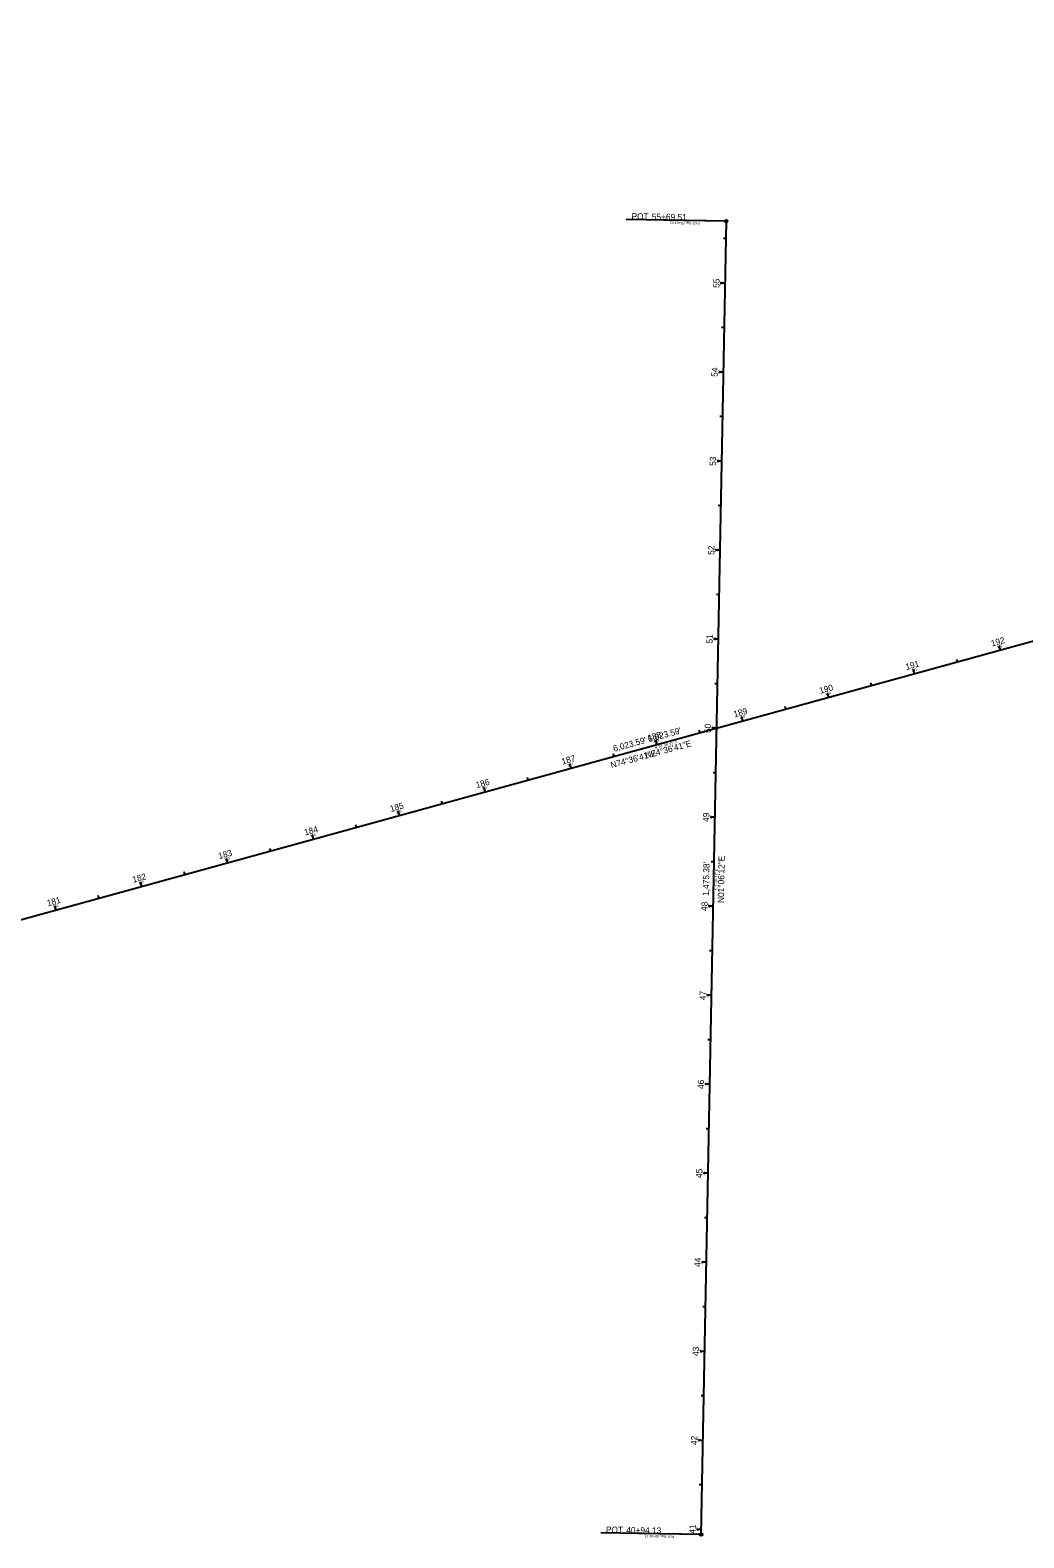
# Model space of a CAD drawing. Extents: x 2129507 to 2138391, y 657622 to 659877.
# Drawn here: x 2131725 to 2132841, y 657622 to 659316 of the extents above; entities that cross this region are included whole.
import ezdxf

# ---------------------------------------------------------------- set-up
doc = ezdxf.new("R2010")
doc.units = 0
for name, color, linetype in [('Default', 7, 'Continuous'), ('GE_X_Alignment_1000_Stations', 7, 'Continuous'), ('GE_X_Alignment_100_Stations', 7, 'Continuous'), ('GE_X_Alignment_500_Stations', 7, 'Continuous'), ('GE_X_CL_20', 7, 'Continuous'), ('MT_P_CL_20', 7, 'Continuous'), ('SC_Scratch1', 7, 'Continuous')]:
    doc.layers.add(name, color=color, linetype=linetype)

msp = doc.modelspace()

# ---------------------------------------------------------------- linework, layer by layer
at = {"layer": 'Default'}
for centre in [(2132506.9, 659101.1), (2132506.9, 659101.1), (2132506.9, 659101.1), (2132505.5, 659031.6), (2132505.5, 659031.6), (2132503.6, 658931.6), (2132501.7, 658831.6), (2132499.8, 658731.6), (2132497.8, 658631.6), (2132814.7, 658619.4), (2132718.3, 658592.9), (2132621.9, 658566.3), (2132621.9, 658566.3), (2132621.9, 658566.3), (2132525.5, 658539.8), (2132440.7, 658516.5), (2132440.7, 658516.5), (2132440.7, 658516.5), (2132440.7, 658516.5), (2132440.7, 658516.5), (2132440.7, 658516.5), (2132495.9, 658531.7), (2132495.9, 658531.7), (2132495.9, 658531.7), (2132429.1, 658513.3), (2132332.7, 658486.7), (2132236.2, 658460.2), (2132139.8, 658433.7), (2132139.8, 658433.7), (2132494, 658431.7), (2132043.4, 658407.1), (2131947, 658380.6), (2131850.6, 658354), (2132492.7, 658363.5), (2132492.7, 658363.5), (2132492.7, 658363.5), (2132492.7, 658363.5), (2132492.7, 658363.5), (2132492.7, 658363.5), (2132492, 658331.7), (2131754.2, 658327.5), (2132490.1, 658231.7), (2132488.2, 658131.7), (2132486.3, 658031.8), (2132486.3, 658031.8), (2132484.3, 657931.8), (2132482.4, 657831.8), (2132480.5, 657731.8), (2132478.5, 657626), (2132478.5, 657626), (2132478.5, 657626), (2132478.6, 657631.8)]:
    msp.add_circle(centre, 0.0000833, dxfattribs=at)
at = {"layer": 'GE_X_Alignment_1000_Stations'}
for p, q in [((2132506.9, 659101.1), (2132394.4, 659103.2)), ((2132505.5, 659031.6), (2132502.5, 659031.6)), ((2132621.9, 658566.3), (2132620.6, 658571.2)), ((2132495.9, 658531.7), (2132490.9, 658531.8)), ((2132139.8, 658433.7), (2132139, 658436.5)), ((2132486.3, 658031.8), (2132483.3, 658031.8)), ((2132478.5, 657626), (2132366, 657628.1))]:
    msp.add_line(p, q, dxfattribs=at)
for centre in [(2132506.9, 659101.1), (2132478.5, 657626)]:
    msp.add_circle(centre, 1.5, dxfattribs=at)
at = {"layer": 'GE_X_Alignment_100_Stations'}
for p, q in [((2132506.9, 659101.1), (2132394.4, 659103.2)), ((2132506.5, 659081.6), (2132503.5, 659081.6)), ((2132505.5, 659031.6), (2132500.5, 659031.7)), ((2132504.6, 658981.6), (2132501.6, 658981.6)), ((2132503.6, 658931.6), (2132498.6, 658931.7)), ((2132502.6, 658881.6), (2132499.6, 658881.7)), ((2132501.7, 658831.6), (2132496.7, 658831.7)), ((2132500.7, 658781.6), (2132497.7, 658781.7)), ((2132499.8, 658731.6), (2132494.8, 658731.7)), ((2132498.8, 658681.6), (2132495.8, 658681.7)), ((2132497.8, 658631.6), (2132492.8, 658631.7)), ((2132814.7, 658619.4), (2132813.4, 658624.2)), ((2132766.5, 658606.1), (2132765.7, 658609)), ((2132718.3, 658592.9), (2132717, 658597.7)), ((2132496.9, 658581.7), (2132493.9, 658581.7)), ((2132621.9, 658566.3), (2132620.6, 658571.2)), ((2132670.1, 658579.6), (2132669.3, 658582.5)), ((2132573.7, 658553.1), (2132572.9, 658556)), ((2132525.5, 658539.8), (2132524.2, 658544.6)), ((2132429.1, 658513.3), (2132427.7, 658518.1)), ((2132477.3, 658526.5), (2132476.5, 658529.4)), ((2132495.9, 658531.7), (2132490.9, 658531.8)), ((2132380.9, 658500), (2132380.1, 658502.9)), ((2132332.7, 658486.7), (2132331.3, 658491.6)), ((2132284.4, 658473.5), (2132283.6, 658476.4)), ((2132494.9, 658481.7), (2132491.9, 658481.7)), ((2132188, 658446.9), (2132187.2, 658449.8)), ((2132236.2, 658460.2), (2132234.9, 658465)), ((2132139.8, 658433.7), (2132138.5, 658438.5)), ((2132494, 658431.7), (2132489, 658431.8)), ((2132091.6, 658420.4), (2132090.8, 658423.3)), ((2132043.4, 658407.1), (2132042.1, 658411.9)), ((2131947, 658380.6), (2131945.7, 658385.4)), ((2131995.2, 658393.9), (2131994.4, 658396.7)), ((2132493, 658381.7), (2132490, 658381.7)), ((2131898.8, 658367.3), (2131898, 658370.2)), ((2131850.6, 658354), (2131849.2, 658358.9)), ((2131754.2, 658327.5), (2131752.8, 658332.3)), ((2131802.4, 658340.8), (2131801.6, 658343.7)), ((2132492, 658331.7), (2132487, 658331.8)), ((2132491.1, 658281.7), (2132488.1, 658281.8)), ((2132490.1, 658231.7), (2132485.1, 658231.8)), ((2132489.2, 658181.7), (2132486.2, 658181.8)), ((2132488.2, 658131.7), (2132483.2, 658131.8)), ((2132487.2, 658081.7), (2132484.2, 658081.8)), ((2132486.3, 658031.8), (2132481.3, 658031.9)), ((2132485.3, 657981.8), (2132482.3, 657981.8)), ((2132484.3, 657931.8), (2132479.3, 657931.9)), ((2132483.4, 657881.8), (2132480.4, 657881.8)), ((2132482.4, 657831.8), (2132477.4, 657831.9)), ((2132481.5, 657781.8), (2132478.5, 657781.9)), ((2132480.5, 657731.8), (2132475.5, 657731.9)), ((2132479.5, 657681.8), (2132476.5, 657681.9)), ((2132478.5, 657626), (2132366, 657628.1)), ((2132478.6, 657631.8), (2132473.6, 657631.9))]:
    msp.add_line(p, q, dxfattribs=at)
for centre in [(2132506.9, 659101.1), (2132478.5, 657626)]:
    msp.add_circle(centre, 1.5, dxfattribs=at)
at = {"layer": 'GE_X_Alignment_500_Stations'}
for p, q in [((2132506.9, 659101.1), (2132394.4, 659103.2)), ((2132505.5, 659031.6), (2132500.5, 659031.7)), ((2132503.6, 658931.6), (2132500.6, 658931.6)), ((2132501.7, 658831.6), (2132498.7, 658831.7)), ((2132499.8, 658731.6), (2132496.8, 658731.7)), ((2132497.8, 658631.6), (2132494.8, 658631.7)), ((2132814.7, 658619.4), (2132813.9, 658622.3)), ((2132718.3, 658592.9), (2132717.5, 658595.8)), ((2132621.9, 658566.3), (2132620.6, 658571.2)), ((2132525.5, 658539.8), (2132524.7, 658542.7)), ((2132495.9, 658531.7), (2132490.9, 658531.8)), ((2132429.1, 658513.3), (2132428.3, 658516.2)), ((2132332.7, 658486.7), (2132331.9, 658489.6)), ((2132236.2, 658460.2), (2132235.4, 658463.1)), ((2132139.8, 658433.7), (2132138.5, 658438.5)), ((2132494, 658431.7), (2132491, 658431.7)), ((2132043.4, 658407.1), (2132042.6, 658410)), ((2131947, 658380.6), (2131946.2, 658383.5)), ((2131850.6, 658354), (2131849.8, 658356.9)), ((2131754.2, 658327.5), (2131753.4, 658330.4)), ((2132492, 658331.7), (2132489, 658331.8)), ((2132490.1, 658231.7), (2132487.1, 658231.8)), ((2132488.2, 658131.7), (2132485.2, 658131.8)), ((2132486.3, 658031.8), (2132481.3, 658031.9)), ((2132484.3, 657931.8), (2132481.3, 657931.8)), ((2132482.4, 657831.8), (2132479.4, 657831.8)), ((2132480.5, 657731.8), (2132477.5, 657731.9)), ((2132478.5, 657626), (2132366, 657628.1)), ((2132478.6, 657631.8), (2132475.6, 657631.9))]:
    msp.add_line(p, q, dxfattribs=at)
for centre in [(2132506.9, 659101.1), (2132478.5, 657626)]:
    msp.add_circle(centre, 1.5, dxfattribs=at)
at = {"layer": 'GE_X_CL_20'}
for p, q in [((2129536.9, 657717.3), (2135344.6, 659315.7)), ((2132505.9, 659101.1), (2132436.4, 659102.4)), ((2132478.5, 657626), (2132506.9, 659101.1)), ((2132506.5, 659081.6), (2132504.5, 659081.6)), ((2132505.5, 659031.6), (2132503.5, 659031.6)), ((2132504.6, 658981.6), (2132502.6, 658981.6)), ((2132503.6, 658931.6), (2132501.6, 658931.6)), ((2132502.6, 658881.6), (2132500.6, 658881.6)), ((2132501.7, 658831.6), (2132499.7, 658831.6)), ((2132500.7, 658781.6), (2132498.7, 658781.7)), ((2132499.8, 658731.6), (2132497.8, 658731.7)), ((2132498.8, 658681.6), (2132496.8, 658681.7)), ((2132497.8, 658631.6), (2132495.8, 658631.7)), ((2132814.7, 658619.4), (2132814.2, 658621.3)), ((2132766.5, 658606.1), (2132766, 658608.1)), ((2132718.3, 658592.9), (2132717.8, 658594.8)), ((2132496.9, 658581.7), (2132494.9, 658581.7)), ((2132621.9, 658566.3), (2132621.4, 658568.3)), ((2132670.1, 658579.6), (2132669.6, 658581.5)), ((2132573.7, 658553.1), (2132573.2, 658555)), ((2132525.5, 658539.8), (2132524.9, 658541.7)), ((2132477.3, 658526.5), (2132476.7, 658528.5)), ((2132495.9, 658531.7), (2132493.9, 658531.7)), ((2132380.9, 658500), (2132380.3, 658501.9)), ((2132429.1, 658513.3), (2132428.5, 658515.2)), ((2132332.7, 658486.7), (2132332.1, 658488.7)), ((2132284.4, 658473.5), (2132283.9, 658475.4)), ((2132494.9, 658481.7), (2132492.9, 658481.7)), ((2132188, 658446.9), (2132187.5, 658448.9)), ((2132236.2, 658460.2), (2132235.7, 658462.1)), ((2132139.8, 658433.7), (2132139.3, 658435.6)), ((2132494, 658431.7), (2132492, 658431.7)), ((2132091.6, 658420.4), (2132091.1, 658422.3)), ((2132043.4, 658407.1), (2132042.9, 658409)), ((2131947, 658380.6), (2131946.5, 658382.5)), ((2131995.2, 658393.9), (2131994.7, 658395.8)), ((2132493, 658381.7), (2132491, 658381.7)), ((2131898.8, 658367.3), (2131898.3, 658369.2)), ((2131850.6, 658354), (2131850, 658356)), ((2131802.4, 658340.8), (2131801.8, 658342.7)), ((2132492, 658331.7), (2132490, 658331.7)), ((2131754.2, 658327.5), (2131753.6, 658329.4)), ((2132491.1, 658281.7), (2132489.1, 658281.7)), ((2132490.1, 658231.7), (2132488.1, 658231.8)), ((2132489.2, 658181.7), (2132487.2, 658181.8)), ((2132488.2, 658131.7), (2132486.2, 658131.8)), ((2132487.2, 658081.7), (2132485.2, 658081.8)), ((2132486.3, 658031.8), (2132484.3, 658031.8)), ((2132485.3, 657981.8), (2132483.3, 657981.8)), ((2132484.3, 657931.8), (2132482.3, 657931.8)), ((2132483.4, 657881.8), (2132481.4, 657881.8)), ((2132482.4, 657831.8), (2132480.4, 657831.8)), ((2132481.5, 657781.8), (2132479.5, 657781.8)), ((2132480.5, 657731.8), (2132478.5, 657731.8)), ((2132479.5, 657681.8), (2132477.5, 657681.9)), ((2132477.5, 657626), (2132407.8, 657627.3)), ((2132478.6, 657631.8), (2132476.6, 657631.9))]:
    msp.add_line(p, q, dxfattribs=at)
for centre in [(2132506.9, 659101.1), (2132478.5, 657626)]:
    msp.add_circle(centre, 1, dxfattribs=at)
at = {"layer": 'MT_P_CL_20'}
for p, q in [((2129536.9, 657717.3), (2135344.6, 659315.7)), ((2132478.5, 657626), (2132506.9, 659101.1))]:
    msp.add_line(p, q, dxfattribs=at)

# ---------------------------------------------------------------- texts
at = {"layer": 'GE_X_Alignment_1000_Stations'}
for s, rotation, p in [('POT', 358.8967, (2132400.3, 659103.2)), ('55+69.51', 358.8967, (2132423.1, 659102.8)), ('190', 15.3886, (2132612.3, 658570.3)), ('50', 88.8967, (2132489.4, 658526.3)), ("6,023.59'", 15.3886, (2132380.8, 658505.2)), ('N74°36\'41"E', 15.3886, (2132377.9, 658486.7)), ('POT', 358.8967, (2132371.5, 657628.1)), ('40+94.13', 358.8967, (2132394.4, 657627.7))]:
    msp.add_text(s, height=7, rotation=rotation, dxfattribs=at).set_placement(p)
at = {"layer": 'GE_X_Alignment_100_Stations'}
for s, rotation, p in [('POT', 358.8967, (2132400.3, 659103.2)), ('55+69.51', 358.8967, (2132423.1, 659102.8)), ('55', 88.8967, (2132499.1, 659026.2)), ('54', 88.8967, (2132497.1, 658926.3)), ('53', 88.8967, (2132495.2, 658826.3)), ('52', 88.8967, (2132493.3, 658726.3)), ('51', 88.8967, (2132491.4, 658626.7)), ('192', 15.3886, (2132805.1, 658623.4)), ('191', 15.3886, (2132709.1, 658597)), ('190', 15.3886, (2132612.3, 658570.3)), ('189', 15.3886, (2132516, 658543.8)), ('50', 88.8967, (2132489.4, 658526.3)), ('N74°36\'41"E', 15.3886, (2132417, 658497.5)), ('188', 15.3886, (2132419.5, 658517.2)), ("6,023.59'", 15.3886, (2132419.9, 658515.9)), ('187', 15.3886, (2132322.9, 658490.7)), ('186', 15.3886, (2132226.6, 658464.2)), ('185', 15.3886, (2132130.2, 658437.6)), ('49', 88.8967, (2132487.5, 658426.4)), ('184', 15.3886, (2132033.9, 658411.1)), ('183', 15.3886, (2131937.4, 658384.6)), ("1,475.38'", 88.8967, (2132487.3, 658343.3)), ('N01°06\'12"E', 88.8967, (2132504.1, 658335.3)), ('182', 15.3886, (2131841, 658358)), ('181', 15.3886, (2131745, 658331.6)), ('48', 88.8967, (2132485.6, 658326.3)), ('47', 88.8967, (2132483.8, 658226.2)), ('46', 88.8967, (2132481.7, 658126.4)), ('45', 88.8967, (2132479.8, 658026.4)), ('44', 88.8967, (2132478, 657926.5)), ('43', 88.8967, (2132476, 657826.5)), ('42', 88.8967, (2132474.1, 657726.5)), ('41', 88.8967, (2132472.2, 657626.9)), ('POT', 358.8967, (2132371.5, 657628.1)), ('40+94.13', 358.8967, (2132394.4, 657627.7))]:
    msp.add_text(s, height=7, rotation=rotation, dxfattribs=at).set_placement(p)
at = {"layer": 'GE_X_Alignment_500_Stations'}
for s, rotation, p in [('POT', 358.8967, (2132400.3, 659103.2)), ('55+69.51', 358.8967, (2132423.1, 659102.8)), ('55', 88.8967, (2132499.1, 659026.2)), ('190', 15.3886, (2132612.3, 658570.3)), ('50', 88.8967, (2132489.4, 658526.3)), ('N74°36\'41"E', 15.3886, (2132417, 658497.5)), ("6,023.59'", 15.3886, (2132419.9, 658515.9)), ('185', 15.3886, (2132130.2, 658437.6)), ('45', 88.8967, (2132479.8, 658026.4)), ('POT', 358.8967, (2132371.5, 657628.1)), ('40+94.13', 358.8967, (2132394.4, 657627.7))]:
    msp.add_text(s, height=7, rotation=rotation, dxfattribs=at).set_placement(p)
at = {"layer": 'GE_X_CL_20'}
for s, rotation, p in [('POT Sta. 55+69.51', 178.8967, (2132476.8, 659100.2)), ('55', 88.8967, (2132502.5, 659029.3)), ('54', 88.8967, (2132500.6, 658929.4)), ('53', 88.8967, (2132498.6, 658829.4)), ('52', 88.8967, (2132496.7, 658729.4)), ('51', 88.8967, (2132494.8, 658629.9)), ('192', 15.3886, (2132811.1, 658621.5)), ('191', 15.3886, (2132715.1, 658595.1)), ('190', 15.3886, (2132618.2, 658568.4)), ('50', 88.8967, (2132492.9, 658529.4)), ('189', 15.3886, (2132521.9, 658541.9)), ('188', 15.3886, (2132425.5, 658515.4)), ('N 74%%d 36\' 41" E', 15.3886, (2132426.9, 658508.3)), ('187', 15.3886, (2132329, 658488.8)), ('186', 15.3886, (2132232.6, 658462.3)), ('185', 15.3886, (2132136.2, 658435.8)), ('49', 88.8967, (2132490.9, 658429.5)), ('184', 15.3886, (2132039.8, 658409.2)), ('183', 15.3886, (2131943.3, 658382.7)), ('N 1%%d 06\' 12" E', 88.8967, (2132496.6, 658349.5)), ('182', 15.3886, (2131847, 658356.2)), ('181', 15.3886, (2131751, 658329.8)), ('48', 88.8967, (2132489, 658329.5)), ('47', 88.8967, (2132487.1, 658229.4)), ('46', 88.8967, (2132485.2, 658129.5)), ('45', 88.8967, (2132483.2, 658029.5)), ('44', 88.8967, (2132481.3, 657929.6)), ('43', 88.8967, (2132479.4, 657829.5)), ('42', 88.8967, (2132477.5, 657729.6)), ('POT Sta. 40+94.13', 178.8967, (2132448.4, 657625.1)), ('41', 88.8967, (2132475.5, 657630.1))]:
    msp.add_text(s, height=2.8, rotation=rotation, dxfattribs=at).set_placement(p)
at = {"layer": 'SC_Scratch1'}
for s, p in [("1,475.38'", (2132487.3, 658343.3)), ("1,475.38'", (2132487.3, 658343.3)), ('N01°06\'12"E', (2132504.1, 658335.3)), ('N01°06\'12"E', (2132504.1, 658335.3))]:
    msp.add_text(s, height=7, rotation=88.8967, dxfattribs=at).set_placement(p)

doc.saveas('drawing.dxf')
